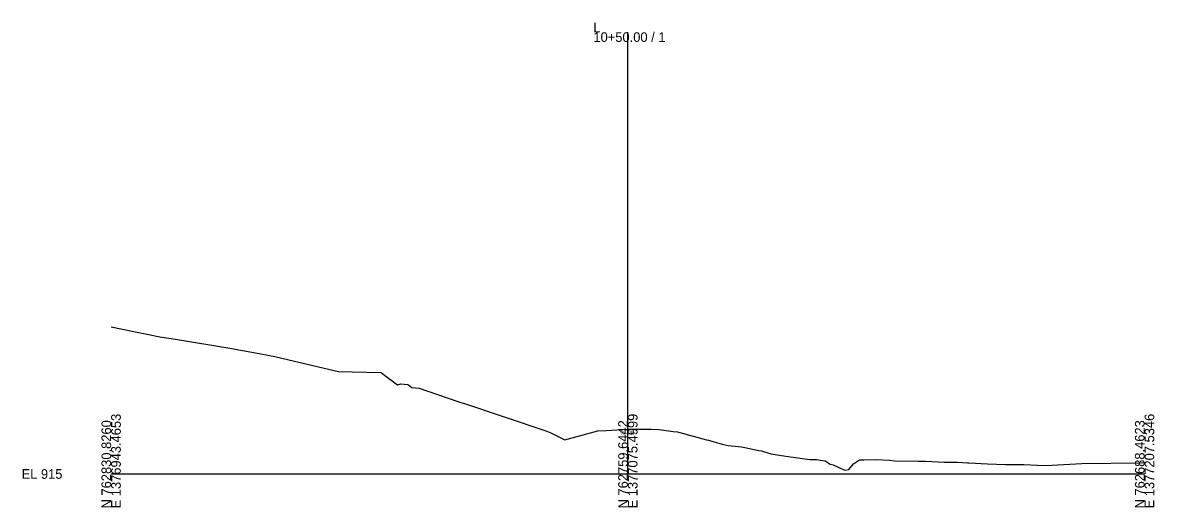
# Model space of a CAD drawing. Extents: x -26 to 303, y -10 to 6523.
# Drawn here: x -25.7 to 302.8, y 490.3 to 631 of the extents above; entities that cross this region are included whole.
import ezdxf

# ---------------------------------------------------------------- set-up
doc = ezdxf.new("R2010")
doc.units = 0
for name, color, linetype in [('Exist Cross Section Cell', 7, 'Continuous'), ('Exist XS Center Line Elevation Label', 7, 'Continuous'), ('Exist XS Ground Line', 7, 'Continuous')]:
    doc.layers.add(name, color=color, linetype=linetype)

msp = doc.modelspace()

# ---------------------------------------------------------------- linework, layer by layer
at = {"layer": 'Exist Cross Section Cell'}
for p, q in [((150, 500), (150, 628.22)), ((0, 500), (150, 500)), ((150, 500), (300, 500))]:
    msp.add_line(p, q, dxfattribs=at)
at = {"layer": 'Exist XS Ground Line'}
for p, q in [((0, 542.74), (14.13, 539.84)), ((14.13, 539.84), (18.71, 539.11)), ((18.71, 539.11), (34.45, 536.48)), ((34.45, 536.48), (43.45, 534.88)), ((43.45, 534.88), (47.49, 534.07)), ((47.49, 534.07), (60.18, 531.06)), ((60.18, 531.06), (66.02, 529.75)), ((66.02, 529.75), (70, 529.68)), ((70, 529.68), (78.39, 529.45)), ((78.39, 529.45), (79.32, 528.66)), ((79.32, 528.66), (83.14, 525.92)), ((83.14, 525.92), (84.07, 526.16)), ((84.07, 526.16), (86.05, 525.98)), ((86.05, 525.98), (86.36, 525.84)), ((86.36, 525.84), (87.26, 525.06)), ((87.26, 525.06), (89.45, 524.87)), ((89.45, 524.87), (100.4, 521.11)), ((100.4, 521.11), (101.47, 520.78)), ((101.47, 520.78), (102.27, 520.53)), ((102.27, 520.53), (126.15, 512.51)), ((132.78, 510.25), (141.31, 512.56)), ((141.31, 512.56), (143.68, 512.66)), ((143.68, 512.66), (150.15, 512.96)), ((150.15, 512.96), (156.74, 512.96)), ((156.74, 512.96), (159.07, 512.92)), ((159.07, 512.92), (163.19, 512.37)), ((126.15, 512.51), (127.63, 511.93)), ((127.63, 511.93), (131.69, 509.94)), ((131.69, 509.94), (132.78, 510.25)), ((163.19, 512.37), (164.37, 512.27)), ((164.37, 512.27), (165.07, 512.01)), ((165.07, 512.01), (172.79, 509.93)), ((172.79, 509.93), (173.37, 509.78)), ((173.37, 509.78), (177.37, 508.64)), ((177.37, 508.64), (179.14, 508.28)), ((179.14, 508.28), (182.95, 507.92)), ((182.95, 507.92), (183.98, 507.66)), ((183.98, 507.66), (188.01, 506.78)), ((188.01, 506.78), (188.82, 506.69)), ((188.82, 506.69), (191.52, 505.88)), ((191.52, 505.88), (195.86, 505.16)), ((195.86, 505.16), (198.7, 504.82)), ((198.7, 504.82), (202.71, 504.2)), ((202.71, 504.2), (204.83, 504.19)), ((204.83, 504.19), (205.8, 504.05)), ((205.8, 504.05), (207.23, 503.86)), ((207.23, 503.86), (208.76, 502.8)), ((208.76, 502.8), (209.56, 502.7)), ((209.56, 502.7), (212.53, 501.32)), ((214.15, 501.33), (215.54, 502.9)), ((215.54, 502.9), (217.28, 504.13)), ((217.28, 504.13), (218.47, 504.12)), ((218.47, 504.12), (222.03, 504.23)), ((222.03, 504.23), (225.92, 504.03)), ((225.92, 504.03), (227.4, 503.85)), ((227.4, 503.85), (234.23, 503.75)), ((234.23, 503.75), (236.4, 503.7)), ((236.4, 503.7), (241.94, 503.44)), ((241.94, 503.44), (242.41, 503.44)), ((242.41, 503.44), (245.68, 503.39)), ((245.68, 503.39), (248.56, 503.23)), ((248.56, 503.23), (249.01, 503.27)), ((249.01, 503.27), (254.38, 502.95)), ((254.38, 502.95), (259.64, 502.78)), ((259.64, 502.78), (264.92, 502.76)), ((264.92, 502.76), (268.88, 502.58)), ((271.34, 502.49), (281.83, 503)), ((281.83, 503), (298.74, 503.28)), ((298.74, 503.28), (300, 503.33)), ((212.53, 501.32), (213.12, 501.1)), ((213.12, 501.1), (214.15, 501.33)), ((268.88, 502.58), (271.34, 502.49))]:
    msp.add_line(p, q, dxfattribs=at)

# ---------------------------------------------------------------- texts
at = {"layer": 'Exist Cross Section Cell'}
for s, p in [('L', (140, 628.22)), ('10+50.00 / 1', (140, 625.42)), ('EL 915', (-26, 498.6))]:
    msp.add_text(s, height=2.8, dxfattribs=at).set_placement(p)
for s, p in [('E 1376943.4653', (2.8, 490)), ('E 1377075.4999', (152.8, 490)), ('E 1377207.5346', (302.8, 490)), ('N 762830.8260', (0, 490)), ('N 762759.6442', (150, 490)), ('N 762688.4623', (300, 490))]:
    msp.add_text(s, height=2.8, rotation=90, dxfattribs=at).set_placement(p)
at = {"layer": 'Exist XS Center Line Elevation Label'}
msp.add_text('927.95', height=0.998, dxfattribs=at).set_placement((147.81, 511.54))

doc.saveas('drawing.dxf')
